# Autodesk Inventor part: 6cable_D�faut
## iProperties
Created: 2011-01
Part Number: 6cable_D�faut
Document SubType Name: Modeling
Designer: eric
Density: 1 g/cm^3
Mass: 1.20855 g
Surface Area: 23.4228 cm^2
Volume: 1.20855 cm^3
Author: eric
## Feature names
1. Base1
